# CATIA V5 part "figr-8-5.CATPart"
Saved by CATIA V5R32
Part number: Part1
Bounding box of the stored display mesh (mm): x 4.549 to 89.781, y -52.238 to 26.36, z 54 to 147.773
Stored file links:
  D:\PROJECTS\Project 2022\CATIA V5 6R 2022\Resources\Part Files\c08_catia_v5_6r2022_prt\figr-8-5.CATPart
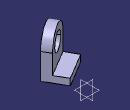
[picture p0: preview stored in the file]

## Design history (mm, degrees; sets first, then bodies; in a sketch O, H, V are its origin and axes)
Body1 (main body)
  Sketch1 on yz-plane, origin (0, 0, 0), H (0, 1, 0), V (0, 0, 1)
    point P1 (-104.4861, 0)
    line L1 (-104.4861, 0) -> (-104.4861, 44.267)
    arc A1 centre (-69.7903, 44.267) radius 34.6958 from (-104.4861, 44.267) to (-35.0946, 44.267) cw
    line L2 (-35.0946, 44.267) -> (-35.0946, 0)
    point P5 (-35.0946, 0)
    line L3 (-35.0946, 0) -> (-104.4861, 0)
    circle A2 centre (-69.7903, 44.267) radius 19.5413
    coincidence: P1 H, P5 H
    vertical: L1 V
    tangency: A1 L1, L2 A1
    horizontal: L3 H
  Pad1: profile Sketch1, direction (1, 0, 0), length 20
  Sketch2 on face of Pad1, origin (0, 0, 0), H (0, -1, 0), V (0, 0, 1)
    point P1 (35.0946, 0)
    line L1 (35.0946, 0) -> (104.4861, 0)
    line L2 (104.4861, 0) -> (104.4861, -15)
    line L3 (104.4861, -15) -> (35.0946, -15)
    line L4 (35.0946, -15) -> (35.0946, 0)
    reference projected line E1 (35.0946, 0) -> (35.0946, 44.267) from edge [face of Pad1 | face of Pad1]
    reference projected line E2 (104.4861, 44.267) -> (104.4861, 0) from edge [face of Pad1 | face of Pad1]
    distance L3 L1 = 15
    coincidence: P1 H, L4 E1, L2 E2
    horizontal: L1 H, L3 H
    vertical: L2 V, L4 V
  Pad2: profile Sketch2, direction (1, 0, 0), length 50
  Translate1: Direction xy-plane, ToTransfor Pad2, Length 69
  Rotate1: Axis edge, ToTransfor Translate1, Angle 121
